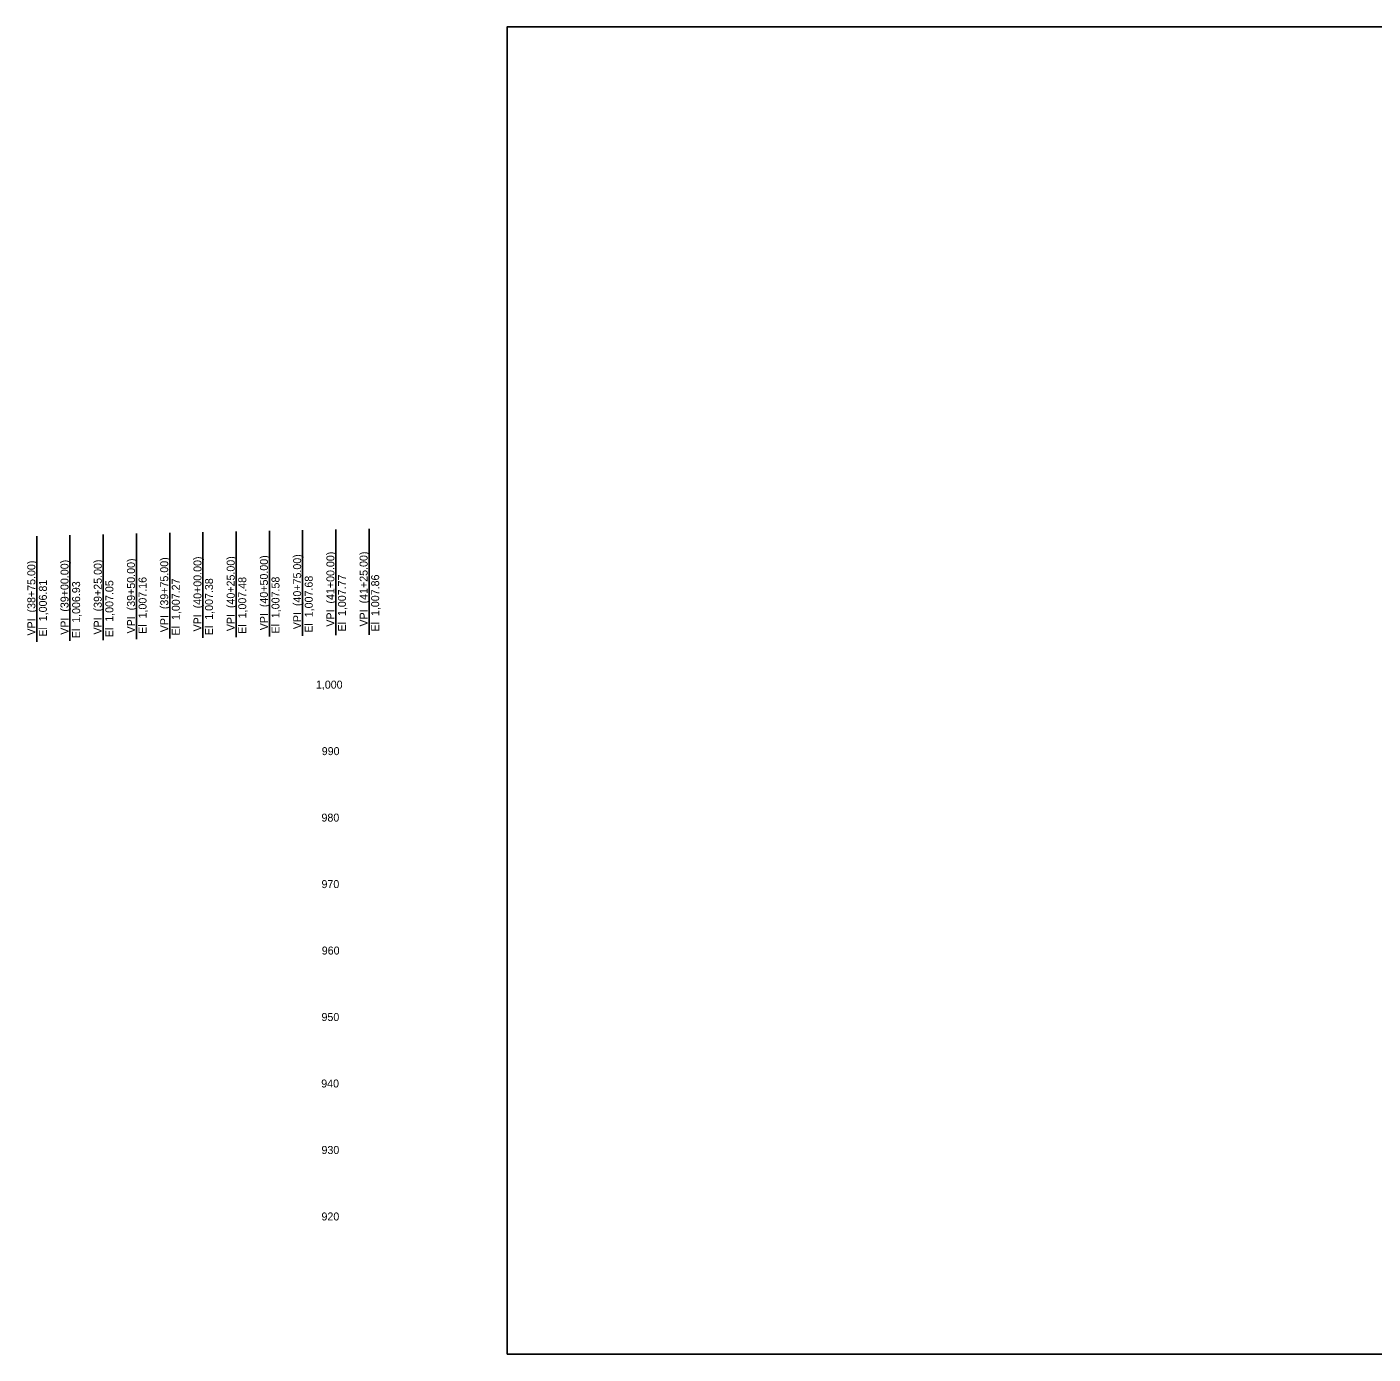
# Model space of a CAD drawing. Extents: x 126 to 16976848, y 7 to 12562190.
# Drawn here: x 16971820 to 16972833, y 12560320 to 12561319 of the extents above; entities that cross this region are included whole.
import ezdxf

# ---------------------------------------------------------------- set-up
doc = ezdxf.new("R2010")
doc.units = 0
for name, color, linetype in [('CLS_Shear_Line', 7, 'Continuous'), ('Default', 7, 'Continuous'), ('RD_EX_Conc-ZZ', 7, 'Continuous'), ('RD_HC_TX_Sta50', 7, 'Continuous')]:
    doc.layers.add(name, color=color, linetype=linetype)

msp = doc.modelspace()

# ---------------------------------------------------------------- linework, layer by layer
at = {"layer": 'CLS_Shear_Line'}
for p, q in [((16972002.7, 12560860.2), (16972002.7, 12560939.7)), ((16972027.7, 12560860.6), (16972027.7, 12560940.2)), ((16972052.7, 12560861.1), (16972052.7, 12560940.6)), ((16972077.7, 12560861.5), (16972077.7, 12560941.1)), ((16971827.7, 12560856.3), (16971827.7, 12560935.8)), ((16971852.7, 12560856.9), (16971852.7, 12560936.4)), ((16971877.7, 12560857.5), (16971877.7, 12560937)), ((16971902.7, 12560858.1), (16971902.7, 12560937.6)), ((16971927.7, 12560858.6), (16971927.7, 12560938.1)), ((16971952.7, 12560859.1), (16971952.7, 12560938.7)), ((16971977.7, 12560859.7), (16971977.7, 12560939.2))]:
    msp.add_line(p, q, dxfattribs=at)
at = {"layer": 'Default'}
msp.add_lwpolyline([(16972181.5, 12560320.5), (16973681.5, 12560320.5), (16973681.5, 12561318.7), (16972181.5, 12561318.7)], close=True, dxfattribs=at)

# ---------------------------------------------------------------- texts
at = {"layer": 'RD_EX_Conc-ZZ'}
for s, p in [('VPI  (40+00.00)', (16971951.6, 12560864)), ('VPI  (40+25.00)', (16971976.6, 12560864.2)), ('VPI  (40+50.00)', (16972001.6, 12560864.9)), ('VPI  (40+75.00)', (16972026.6, 12560865.7)), ('VPI  (41+00.00)', (16972051.6, 12560867.6)), ('VPI  (41+25.00)', (16972076.6, 12560867.7)), ('VPI  (38+75.00)', (16971826.6, 12560860.9)), ('VPI  (39+00.00)', (16971851.6, 12560861.5)), ('VPI  (39+25.00)', (16971876.6, 12560861.7)), ('VPI  (39+50.00)', (16971901.6, 12560862.5)), ('VPI  (39+75.00)', (16971926.6, 12560863.4)), ('El  1,006.81', (16971835.3, 12560860.1)), ('El  1,006.93', (16971860.3, 12560858.9)), ('El  1,007.05', (16971885.3, 12560859.7)), ('El  1,007.16', (16971910.3, 12560862.2)), ('El  1,007.27', (16971935.3, 12560861)), ('El  1,007.38', (16971960.3, 12560861.2)), ('El  1,007.48', (16971985.3, 12560862.2)), ('El  1,007.58', (16972010.3, 12560862.4)), ('El  1,007.68', (16972035.3, 12560863.1)), ('El  1,007.77', (16972060.3, 12560864)), ('El  1,007.86', (16972085.3, 12560864))]:
    msp.add_text(s, height=6, rotation=90, dxfattribs=at).set_placement(p)
at = {"layer": 'RD_HC_TX_Sta50'}
for s, p in [('1,000', (16972037.7, 12560821)), ('990', (16972042.1, 12560771)), ('980', (16972041.9, 12560721)), ('970', (16972041.9, 12560671)), ('960', (16972042.1, 12560621)), ('950', (16972041.9, 12560571)), ('940', (16972041.7, 12560521)), ('930', (16972041.9, 12560471)), ('920', (16972041.9, 12560421))]:
    msp.add_text(s, height=6, dxfattribs=at).set_placement(p)

doc.saveas('drawing.dxf')
